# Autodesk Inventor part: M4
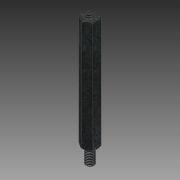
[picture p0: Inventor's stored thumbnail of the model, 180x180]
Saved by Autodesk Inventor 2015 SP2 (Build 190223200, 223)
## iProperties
Created: 2012-08
Part Number: M4
Material: Stahl
Document SubType Name: Modeling
Designer: rYan
Density: 7.85 g/cm^3
Mass: 1.74537 g
Surface Area: 3.04272 cm^2
Volume: 0.22234 cm^3
Appearance: Platte
Author: rYan
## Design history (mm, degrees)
derived "Abstandsbolzen Typ B.ipt"
feature "Volumenkörper1::Abstandsbolzen Typ B.ipt"
tag "Bezeichnung1"
node "Volumenkörper1"
other parameters: "SW" = 7, "L" = 55, "d2" = 0, "l_" = 9, "d9" = 118 deg, "GA_" = 4, "A_" = 8, "d13" = 0, "d17" = 0.25, "d20" = 45 deg
